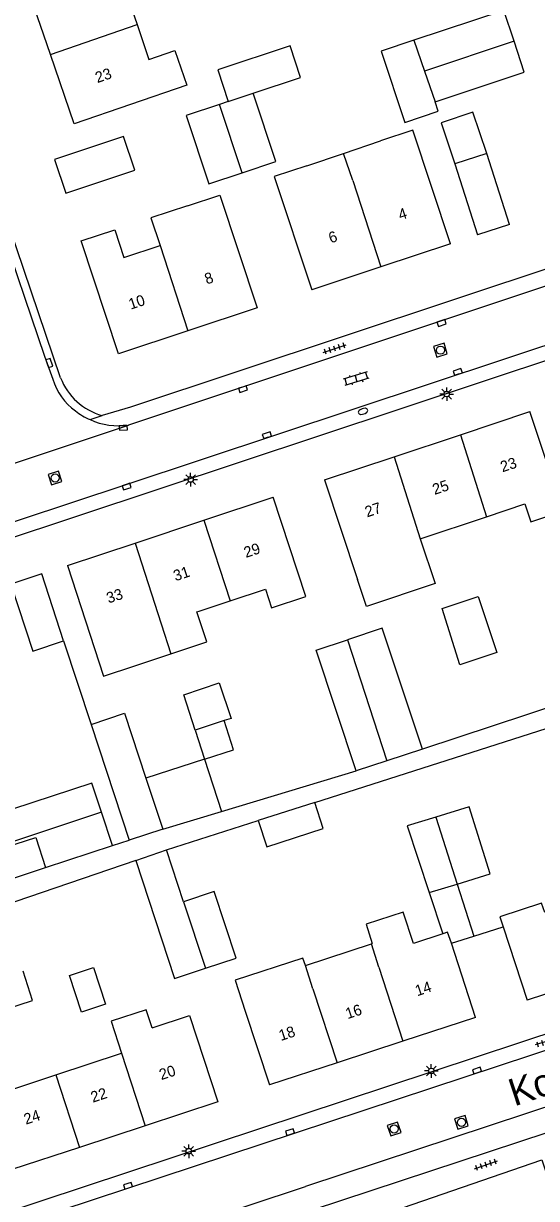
# Model space of a CAD drawing. Extents: x 136000 to 138005, y 398500 to 400500.
# Drawn here: x 137414.9 to 137462, y 398576 to 398683.8 of the extents above; entities that cross this region are included whole.
import ezdxf

# ---------------------------------------------------------------- set-up
doc = ezdxf.new("R2010")
doc.units = 0
for name, color, linetype in [('gg-afsc-erfafscheiding', 7, 'Continuous'), ('gg-afsc-hekwerk', 7, 'Continuous'), ('gg-anno-huisnummerreeks BGT', 7, 'Continuous'), ('gg-anno-openbare ruimte label', 7, 'Continuous'), ('gg-bbg-bijgebouw', 7, 'Continuous'), ('gg-bbg-gedigitaliseerde bebouwing', 7, 'Continuous'), ('gg-bbg-gedigitaliseerde bijgebouw', 7, 'Continuous'), ('gg-bbg-hoofdgebouw', 7, 'Continuous'), ('gg-bbg-luifel en loopbrug', 7, 'Continuous'), ('gg-bbg-tussenscheiding', 7, 'Continuous'), ('gg-knt-verharding', 7, 'Continuous'), ('gt-grn-weggrens', 7, 'Continuous'), ('gt-symb-brandkraan', 7, 'Continuous'), ('gt-symb-klinker verharding', 7, 'Continuous'), ('gt-symb-kolk', 7, 'Continuous'), ('gt-symb-lichtmast', 7, 'Continuous'), ('gt-symb-rioolschacht', 7, 'Continuous'), ('gt-symb-tegel verharding', 7, 'Continuous')]:
    doc.layers.add(name, color=color, linetype=linetype)

# ---------------------------------------------------------------- blocks, each defined once
blk = doc.blocks.new('gt0-KOLK')
at = {"layer": 'gt-symb-kolk'}
blk.add_lwpolyline([(0, 0), (0.37, 0), (0.37, 0.4), (-0.38, 0.4), (-0.38, 0), (0, 0)], dxfattribs=at)
blk = doc.blocks.new('gt0-TEG1')
at = {"layer": 'gt-symb-tegel verharding'}
for p, q in [((-1.12, 0), (1.12, 0)), ((-0.9, -0.25), (-0.9, 0.25)), ((-0.45, -0.25), (-0.45, 0.25)), ((0, -0.25), (0, 0.25)), ((0.45, -0.25), (0.45, 0.25)), ((0.9, -0.25), (0.9, 0.25))]:
    blk.add_line(p, q, dxfattribs=at)
blk = doc.blocks.new('gt0-KL1')
at = {"layer": 'gt-symb-klinker verharding'}
for p, q in [((-1.15, 0.3), (1.15, 0.3)), ((-1, -0.3), (-1, 0.3)), ((-0.5, 0.3), (-0.5, 0.45)), ((0, -0.3), (0, 0.3)), ((0.5, 0.3), (0.5, 0.45)), ((1, -0.3), (1, 0.3)), ((-1.15, -0.3), (1.15, -0.3)), ((-0.5, -0.45), (-0.5, -0.3)), ((0.5, -0.45), (0.5, -0.3))]:
    blk.add_line(p, q, dxfattribs=at)
blk = doc.blocks.new('gt0-BR')
at = {"layer": 'gt-symb-brandkraan'}
for centre, radius, start, end in [((-0.24, 0), 0.206, 107.5669, 252.4331), ((0.6, -2.66), 3, 106.892, 107.5669), ((0, -0.69), 0.938, 73.108, 106.892), ((-0.6, -2.66), 3, 72.4331, 73.108), ((0.24, 0), 0.206, 287.567, 72.4331), ((0.6, 2.66), 3, 252.4331, 253.108), ((0, 0.69), 0.938, 253.108, 286.8921), ((-0.6, 2.66), 3, 286.8921, 287.567)]:
    blk.add_arc(centre, radius, start, end, dxfattribs=at)
blk = doc.blocks.new('gt0-RS')
at = {"layer": 'gt-symb-rioolschacht'}
blk.add_lwpolyline([(-0.5, -0.5), (0.5, -0.5), (0.5, 0.5), (-0.5, 0.5)], close=True, dxfattribs=at)
blk.add_circle((0, 0), 0.375, dxfattribs=at)
blk = doc.blocks.new('gt0-LMAST')
at = {"layer": 'gt-symb-lichtmast'}
for p, q in [((-0.18, 0.17), (-0.45, 0.44)), ((-0.01, 0.25), (-0.01, 0.62)), ((0.17, 0.17), (0.44, 0.44)), ((-0.26, 0), (-0.63, 0)), ((-0.18, -0.18), (-0.45, -0.45)), ((-0.01, -0.25), (-0.01, -0.63)), ((0.44, -0.45), (0.17, -0.18)), ((0.24, 0), (0.62, 0))]:
    blk.add_line(p, q, dxfattribs=at)
blk.add_circle((-0.01, 0), 0.25, dxfattribs=at)

msp = doc.modelspace()

# ---------------------------------------------------------------- linework, layer by layer
at = {"layer": 'gg-afsc-erfafscheiding'}
for p, q in [((137418.57, 398627.15), (137421.09, 398619.48)), ((137482.08, 398627.26), (137451.51, 398617.22)), ((137441.63, 398612.32), (137472.81, 398622.27)), ((137433.06, 398611.5), (137445.44, 398615.23)), ((137428.03, 398607.98), (137436.43, 398610.66)), ((137423.05, 398608.36), (137424.6, 398608.87)), ((137425.2, 398607.01), (137412.93, 398602.8))]:
    msp.add_line(p, q, dxfattribs=at)
at = {"layer": 'gg-afsc-hekwerk'}
msp.add_line((137456.23, 398600.06), (137458.92, 398600.92), dxfattribs=at)
at = {"layer": 'gg-bbg-bijgebouw'}
for p, q in [((137459.51, 398665.33), (137456.58, 398664.39)), ((137421.09, 398619.48), (137424.17, 398620.5)), ((137416.92, 398606.35), (137423.05, 398608.36))]:
    msp.add_line(p, q, dxfattribs=at)
for points in [[(137417.74, 398671.29), (137418.77, 398668.21), (137425.11, 398670.32), (137424.08, 398673.4), (137417.74, 398671.29)], [(137418.57, 398627.15), (137416.56, 398633.29), (137413.72, 398632.35)], [(137413.72, 398632.35), (137415.74, 398626.21), (137418.57, 398627.15)], [(137407.67, 398606.67), (137407.74, 398606.45), (137416.01, 398609.11), (137416.92, 398606.35)], [(137408.71, 398594.85), (137409.57, 398592.18), (137415.72, 398594.16), (137414.85, 398596.84)]]:
    msp.add_lwpolyline(points, dxfattribs=at)
at = {"layer": 'gg-bbg-gedigitaliseerde bebouwing'}
for p, q in [((137444.27, 398671.85), (137447.66, 398672.99)), ((137440.9, 398670.71), (137444.27, 398671.85)), ((137442.52, 398641.9), (137445.55, 398632.78)), ((137451.31, 398636.51), (137457.4, 398638.53)), ((137431.01, 398629.85), (137433.86, 398630.8)), ((137428.41, 398625.94), (137431.72, 398627.04)), ((137425.11, 398624.84), (137428.41, 398625.94)), ((137422.24, 398623.89), (137425.11, 398624.84)), ((137453.38, 398600.28), (137450.68, 398599.39)), ((137453.83, 398600.43), (137453.38, 398600.28)), ((137454.17, 398599.41), (137453.83, 398600.43)), ((137440.77, 398597.36), (137446.83, 398599.36)), ((137446.83, 398599.36), (137446.91, 398599.38)), ((137435.25, 398593.19), (137437.48, 398586.41)), ((137417.86, 398587.34), (137423.88, 398589.33)), ((137411.63, 398585.28), (137417.86, 398587.34))]:
    msp.add_line(p, q, dxfattribs=at)
for points in [[(137415.19, 398687.25), (137425.51, 398690.78), (137426.58, 398687.65), (137424.23, 398686.84), (137425.32, 398683.66)], [(137425.32, 398683.66), (137426.41, 398680.47), (137428.79, 398681.29), (137429.89, 398678.1), (137419.54, 398674.56)], [(137454.08, 398663.54), (137450.63, 398673.98), (137447.66, 398672.99)], [(137440.9, 398670.71), (137437.91, 398669.73), (137441.35, 398659.33)], [(137429.94, 398667.05), (137432.91, 398668.03), (137436.34, 398657.67)], [(137429.94, 398667.05), (137426.59, 398665.94), (137427.44, 398663.4)], [(137423.26, 398664.84), (137424.11, 398662.29), (137427.44, 398663.4)], [(137457.4, 398638.53), (137460.92, 398639.7), (137461.47, 398638.05), (137464.43, 398639.03), (137461.39, 398648.17)], [(137433.86, 398630.8), (137437.11, 398631.87), (137437.67, 398630.18), (137440.8, 398631.22), (137437.8, 398640.31)], [(137451.31, 398636.51), (137452.68, 398632.39), (137446.38, 398630.29), (137445.55, 398632.78)], [(137431.72, 398627.04), (137430.81, 398629.79), (137431.01, 398629.85)], [(137422.04, 398611.42), (137421.16, 398614.09), (137413.87, 398611.69), (137412.93, 398614.55), (137411.27, 398614.01)], [(137465.08, 398603.01), (137462.74, 398602.23), (137462.45, 398603.09), (137458.62, 398601.83), (137458.92, 398600.92)], [(137450.68, 398599.39), (137449.74, 398602.26), (137446.34, 398601.15), (137446.91, 398599.38)], [(137440.77, 398597.36), (137440.54, 398598.05), (137434.33, 398596.01), (137435.25, 398593.19)], [(137426.7, 398591.65), (137426.16, 398593.3), (137422.93, 398592.25), (137423.88, 398589.33)], [(137426.7, 398591.65), (137430.13, 398592.78), (137432.73, 398584.87)]]:
    msp.add_lwpolyline(points, dxfattribs=at)
at = {"layer": 'gg-bbg-gedigitaliseerde bijgebouw'}
for p, q in [((137433.68, 398676.6), (137432.89, 398676.34)), ((137457.42, 398671.84), (137454.5, 398670.9)), ((137459.51, 398665.33), (137457.42, 398671.84)), ((137454.5, 398670.9), (137456.58, 398664.39)), ((137430.66, 398618.94), (137429.61, 398622.2)), ((137424.17, 398620.5), (137426.13, 398614.54)), ((137421.09, 398619.48), (137424.6, 398608.87)), ((137430.66, 398618.94), (137431.52, 398616.28)), ((137451.51, 398617.22), (137448.24, 398616.15)), ((137448.24, 398616.15), (137445.44, 398615.23)), ((137426.13, 398614.54), (137427.67, 398609.88)), ((137423.05, 398608.36), (137422.04, 398611.42)), ((137441.63, 398612.32), (137436.43, 398610.66)), ((137427.67, 398609.88), (137424.6, 398608.87)), ((137425.2, 398607.01), (137428.03, 398607.98)), ((137429.59, 398603.22), (137428.03, 398607.98)), ((137452.14, 398604.05), (137454.7, 398604.83))]:
    msp.add_line(p, q, dxfattribs=at)
for points in [[(137459.94, 398682.13), (137459, 398684.96), (137450.74, 398682.22)], [(137435.98, 398677.36), (137440.32, 398678.8), (137439.36, 398681.7), (137432.72, 398679.5), (137433.68, 398676.6)], [(137450.74, 398682.22), (137447.72, 398681.22), (137449.89, 398674.69), (137452.97, 398675.71), (137452.68, 398676.59)], [(137452.68, 398676.59), (137460.87, 398679.31), (137459.94, 398682.13)], [(137434.97, 398670.07), (137438.06, 398671.1), (137435.98, 398677.36)], [(137432.89, 398676.34), (137429.81, 398675.31), (137431.89, 398669.05), (137434.97, 398670.07)], [(137453.33, 398630.12), (137456.64, 398631.22), (137458.35, 398626.07), (137454.96, 398624.94), (137453.33, 398630.12)], [(137451.51, 398617.22), (137447.82, 398628.3), (137444.62, 398627.23)], [(137445.44, 398615.23), (137441.76, 398626.28), (137444.62, 398627.23)], [(137429.61, 398622.2), (137432.86, 398623.28), (137433.94, 398620.03), (137433.32, 398619.83)], [(137431.52, 398616.28), (137434.18, 398617.14), (137433.32, 398619.83)], [(137436.43, 398610.66), (137437.22, 398608.24), (137442.41, 398609.93), (137441.63, 398612.32)], [(137454.7, 398604.83), (137457.74, 398605.76), (137455.8, 398611.91), (137452.73, 398610.98)], [(137452.73, 398610.98), (137450.12, 398610.19), (137452.14, 398604.05)], [(137425.2, 398607.01), (137428.75, 398596.19), (137431.59, 398597.12)], [(137431.59, 398597.12), (137434.4, 398598.04), (137432.39, 398604.14), (137429.59, 398603.22)], [(137419.12, 398596.45), (137421.33, 398597.17), (137422.42, 398593.82), (137420.21, 398593.1), (137419.12, 398596.45)]]:
    msp.add_lwpolyline(points, dxfattribs=at)
at = {"layer": 'gg-bbg-hoofdgebouw'}
for p, q in [((137417.37, 398680.91), (137415.19, 398687.25)), ((137419.54, 398674.56), (137417.37, 398680.91)), ((137454.08, 398663.54), (137447.71, 398661.43)), ((137447.71, 398661.43), (137441.35, 398659.33)), ((137436.34, 398657.67), (137429.98, 398655.56)), ((137455.01, 398646.05), (137461.39, 398648.17)), ((137448.93, 398644.03), (137455.01, 398646.05)), ((137442.52, 398641.9), (137448.93, 398644.03)), ((137431.43, 398638.2), (137437.8, 398640.31)), ((137425.13, 398636.11), (137431.43, 398638.2)), ((137418.94, 398634.06), (137425.13, 398636.11)), ((137418.94, 398634.06), (137422.24, 398623.89)), ((137458.92, 398600.92), (137461.14, 398594.19)), ((137456.39, 398592.61), (137454.17, 398599.41)), ((137467.25, 398596.2), (137461.14, 398594.19)), ((137456.39, 398592.61), (137449.72, 398590.43)), ((137449.72, 398590.43), (137443.68, 398588.44)), ((137443.68, 398588.44), (137437.48, 398586.41)), ((137432.73, 398584.87), (137426.05, 398582.67)), ((137426.05, 398582.67), (137420.02, 398580.69))]:
    msp.add_line(p, q, dxfattribs=at)
for points in [[(137429.98, 398655.56), (137423.61, 398653.45), (137420.19, 398663.82), (137423.26, 398664.84)], [(137420.02, 398580.69), (137413.83, 398578.65), (137411.63, 398585.28)]]:
    msp.add_lwpolyline(points, dxfattribs=at)
at = {"layer": 'gg-bbg-luifel en loopbrug'}
for p, q in [((137431.52, 398616.28), (137426.13, 398614.54)), ((137431.52, 398616.28), (137433.06, 398611.5)), ((137427.67, 398609.88), (137433.06, 398611.5)), ((137452.14, 398604.05), (137453.38, 398600.28)), ((137454.7, 398604.83), (137456.23, 398600.06)), ((137454.17, 398599.41), (137456.23, 398600.06))]:
    msp.add_line(p, q, dxfattribs=at)
msp.add_lwpolyline([(137457.42, 398671.84), (137456.14, 398675.62), (137453.23, 398674.64), (137454.5, 398670.9)], dxfattribs=at)
at = {"layer": 'gg-bbg-tussenscheiding'}
for p, q in [((137417.37, 398680.91), (137425.32, 398683.66)), ((137450.74, 398682.22), (137451.71, 398679.4)), ((137459.94, 398682.13), (137451.71, 398679.4)), ((137451.71, 398679.4), (137452.68, 398676.59)), ((137433.68, 398676.6), (137435.98, 398677.36)), ((137434.97, 398670.07), (137432.89, 398676.34)), ((137445.11, 398669.36), (137444.27, 398671.85)), ((137445.11, 398669.36), (137447.71, 398661.43)), ((137427.44, 398663.4), (137429.98, 398655.56)), ((137455.01, 398646.05), (137457.4, 398638.53)), ((137448.93, 398644.03), (137451.31, 398636.51)), ((137431.43, 398638.2), (137433.86, 398630.8)), ((137425.13, 398636.11), (137427.52, 398628.7)), ((137427.52, 398628.7), (137428.41, 398625.94)), ((137444.62, 398627.23), (137448.24, 398616.15)), ((137433.32, 398619.83), (137430.66, 398618.94)), ((137422.04, 398611.42), (137407.67, 398606.67)), ((137452.73, 398610.98), (137454.7, 398604.83)), ((137429.59, 398603.22), (137431.59, 398597.12)), ((137447.52, 398597.22), (137446.83, 398599.36)), ((137441.46, 398595.23), (137440.77, 398597.36)), ((137447.52, 398597.22), (137449.72, 398590.43)), ((137441.46, 398595.23), (137443.68, 398588.44)), ((137423.88, 398589.33), (137426.05, 398582.67)), ((137417.86, 398587.34), (137420.02, 398580.69))]:
    msp.add_line(p, q, dxfattribs=at)
at = {"layer": 'gg-knt-verharding'}
for p, q in [((137409.29, 398675.3), (137416.83, 398653.26)), ((137392.26, 398629.47), (137509.07, 398668.17)), ((137416.83, 398653.26), (137417.57, 398651.14)), ((137513.8, 398607.93), (137411.02, 398573.95)), ((137397.18, 398599.88), (137416.92, 398606.35)), ((137492.15, 398594.03), (137440.79, 398577.1)), ((137426.33, 398572.33), (137440.79, 398577.1))]:
    msp.add_line(p, q, dxfattribs=at)
for points in [[(137418.3, 398651.27), (137410.19, 398675.1), (137411.69, 398678.35), (137391.4, 398737.81), (137389.27, 398737.03), (137376.71, 398774.53), (137376.43, 398774.43), (137368.43, 398798.39)], [(137394.91, 398631.77), (137424.3, 398641.48), (137507.86, 398669.19)], [(137483.93, 398668.22), (137424.7, 398648.56), (137422.1, 398647.81)], [(137484.84, 398666.95), (137469.96, 398662.05), (137424.52, 398646.93)], [(137415.11, 398573.87), (137470.91, 398592.26), (137516.36, 398607.29), (137529.7, 398611.73)], [(137441.43, 398574.95), (137492.86, 398591.91), (137492.15, 398594.03)], [(137425.16, 398566.7), (137462.49, 398579.53), (137462.89, 398578.34), (137466.06, 398579.48)]]:
    msp.add_lwpolyline(points, dxfattribs=at)
for centre, radius, start, end in [((137423.62, 398653.3), 5.7, 200.8948, 254.4844), ((137422.94, 398652.8), 5.62, 197.1786, 234.3354), ((137423.63, 398653.36), 6.49, 232.2636, 246.0362), ((137423.63, 398653.35), 6.48, 246.0538, 277.9048)]:
    msp.add_arc(centre, radius, start, end, dxfattribs=at)
at = {"layer": 'gt-grn-weggrens'}
for p, q in [((137421, 398647.43), (137422.1, 398647.81)), ((137409.64, 398641.98), (137424.52, 398646.93))]:
    msp.add_line(p, q, dxfattribs=at)

# ---------------------------------------------------------------- block references
at = {"layer": 'gt-symb-brandkraan', "rotation": -161.94544753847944}
msp.add_blockref('gt0-BR', (137446.06, 398648.19), dxfattribs=at)
at = {"layer": 'gt-symb-klinker verharding', "rotation": -163.26783977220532}
msp.add_blockref('gt0-KL1', (137445.42, 398651.19), dxfattribs=at)
at = {"layer": 'gt-symb-kolk'}
for p, rotation in [((137453.2, 398656.48), -161.6375315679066), ((137417.07, 398652.56), -71.09393900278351), ((137454.83, 398651.62), 18.3624684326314), ((137434.98, 398650.42), -161.691931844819), ((137424.04, 398646.88), -176.3879250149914), ((137437.3, 398645.81), 18.308068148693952), ((137424.3, 398641.48), -161.58316555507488), ((137456.6, 398587.55), 18.181268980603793), ((137439.42, 398581.9), 18.308068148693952), ((137424.55, 398576.98), 18.23569146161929)]:
    msp.add_blockref('gt0-KOLK', p, dxfattribs=dict(at, rotation=rotation))
at = {"layer": 'gt-symb-lichtmast'}
for p in [(137453.75, 398649.77), (137430.24, 398641.94), (137452.34, 398587.7), (137430.07, 398580.34)]:
    msp.add_blockref('gt0-LMAST', p, dxfattribs=at)
at = {"layer": 'gt-symb-rioolschacht'}
for p, rotation in [((137453.17, 398653.8), -162.36228444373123), ((137417.79, 398642.08), -162.05443695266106), ((137455.1, 398582.98), -162.41690287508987), ((137448.92, 398582.38), -161.94544753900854)]:
    msp.add_blockref('gt0-RS', p, dxfattribs=dict(at, rotation=rotation))
at = {"layer": 'gt-symb-tegel verharding'}
for p, rotation in [((137443.46, 398653.94), 18.23569146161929), ((137462.94, 398590.41), -162.72457972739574), ((137457.35, 398579.09), 18.960251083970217)]:
    msp.add_blockref('gt0-TEG1', p, dxfattribs=dict(at, rotation=rotation))

# ---------------------------------------------------------------- texts
at = {"layer": 'gg-anno-huisnummerreeks BGT'}
for s, rotation, p in [('23', 18.9, (137421.67, 398678.29)), ('4', 18.3, (137449.49, 398665.71)), ('6', 18.3, (137443.09, 398663.59)), ('8', 18.4, (137431.71, 398659.82)), ('10', 18.4, (137424.73, 398657.51)), ('23', 18.4, (137458.86, 398642.59)), ('25', 18.4, (137452.63, 398640.52)), ('27', 18.4, (137446.43, 398638.46)), ('29', 18.4, (137435.31, 398634.74)), ('31', 18.4, (137428.84, 398632.6)), ('33', 18.4, (137422.7, 398630.56)), ('14', 18.2, (137451.03, 398594.54)), ('16', 18.2, (137444.64, 398592.44)), ('18', 18.2, (137438.52, 398590.44)), ('20', 18.2, (137427.54, 398586.85)), ('22', 18.2, (137421.25, 398584.78)), ('24', 18.2, (137415.11, 398582.76))]:
    msp.add_text(s, height=1, rotation=rotation, dxfattribs=at).set_placement(p)
at = {"layer": 'gg-anno-openbare ruimte label'}
msp.add_text('Korenbloemstraat', height=2.5, rotation=18.2, dxfattribs=at).set_placement((137459.95, 398584.44))

doc.saveas('drawing.dxf')
